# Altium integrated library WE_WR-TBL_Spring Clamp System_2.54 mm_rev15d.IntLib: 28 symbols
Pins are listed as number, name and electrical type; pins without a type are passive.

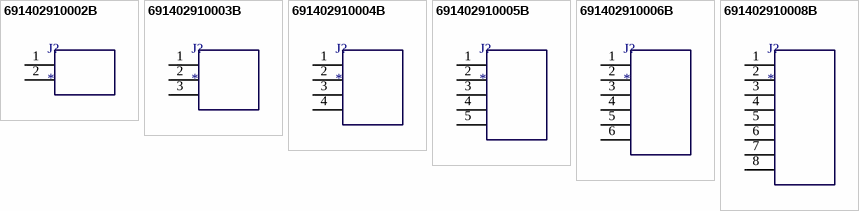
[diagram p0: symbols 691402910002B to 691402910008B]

## 691402910002B
designator J?
WR-TBL Screwless Entry Horizontal,Serie 4029 B - 2.54 mm; Manufacturer: Würth Elektronik eiSos GmbH; partNo: 691402910002B; ComponentLink1 Description: Manufacturer; ComponentLink2 Description: Datasheet; NoPins: 4
footprint 691402910002B
pins: 1  , 2  

## 691402910003B
designator J?
WR-TBL Screwless Entry Horizontal,Serie 4029 B - 2.54 mm; Manufacturer: Würth Elektronik eiSos GmbH; partNo: 691402910003B; ComponentLink1 Description: Manufacturer; ComponentLink2 Description: Datasheet; NoPins: 6
footprint 691402910003B
pins: 1  , 2  , 3  

## 691402910004B
designator J?
WR-TBL Screwless Entry Horizontal,Serie 4029 B - 2.54 mm; Manufacturer: Würth Elektronik eiSos GmbH; partNo: 691402910004B; ComponentLink1 Description: Manufacturer; ComponentLink2 Description: Datasheet; NoPins: 8
footprint 691402910004B
pins: 1  , 2  , 3  , 4  

## 691402910005B
designator J?
WR-TBL Screwless Entry Horizontal,Serie 4029 B - 2.54 mm; Manufacturer: Würth Elektronik eiSos GmbH; partNo: 691402910005B; ComponentLink1 Description: Manufacturer; ComponentLink2 Description: Datasheet; NoPins: 10
footprint 691402910005B
pins: 1  , 2  , 3  , 4  , 5  

## 691402910006B
designator J?
WR-TBL Screwless Entry Horizontal,Serie 4029 B - 2.54 mm; Manufacturer: Würth Elektronik eiSos GmbH; partNo: 691402910006B; ComponentLink1 Description: Manufacturer; ComponentLink2 Description: Datasheet; NoPins: 12
footprint 691402910006B
pins: 1  , 2  , 3  , 4  , 5  , 6  

## 691402910008B
designator J?
WR-TBL Screwless Entry Horizontal,Serie 4029 B - 2.54 mm; Manufacturer: Würth Elektronik eiSos GmbH; partNo: 691402910008B; ComponentLink1 Description: Manufacturer; ComponentLink2 Description: Datasheet; NoPins: 16
footprint 691402910008B
pins: 1  , 2  , 3  , 4  , 5  , 6  , 7  , 8  


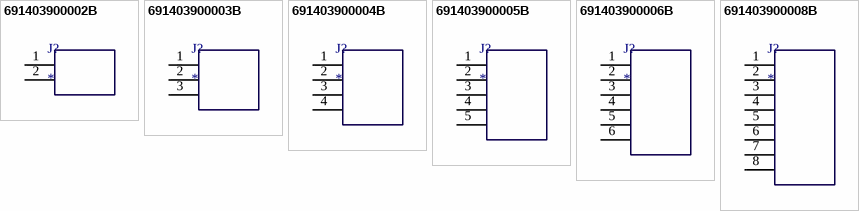
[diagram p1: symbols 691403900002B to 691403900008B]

## 691403900002B
designator J?
WR-TBL Screwless Entry Vertical,Serie 4039 B - 2.54 mm; Manufacturer: Würth Elektronik eiSos GmbH; partNo: 691403900002B; ComponentLink1 Description: Manufacturer; ComponentLink2 Description: Datasheet; NoPins: 4
footprint 691403900002B
pins: 1  , 2  

## 691403900003B
designator J?
WR-TBL Screwless Entry Vertical,Serie 4039 B - 2.54 mm; Manufacturer: Würth Elektronik eiSos GmbH; partNo: 691403900003B; ComponentLink1 Description: Manufacturer; ComponentLink2 Description: Datasheet; NoPins: 6
footprint 691403900003B
pins: 1  , 2  , 3  

## 691403900004B
designator J?
WR-TBL Screwless Entry Vertical,Serie 4039 B - 2.54 mm; Manufacturer: Würth Elektronik eiSos GmbH; partNo: 691403900004B; ComponentLink1 Description: Manufacturer; ComponentLink2 Description: Datasheet; NoPins: 8
footprint 691403900004B
pins: 1  , 2  , 3  , 4  

## 691403900005B
designator J?
WR-TBL Screwless Entry Vertical,Serie 4039 B - 2.54 mm; Manufacturer: Würth Elektronik eiSos GmbH; partNo: 691403900005B; ComponentLink1 Description: Manufacturer; ComponentLink2 Description: Datasheet; NoPins: 10
footprint 691403900005B
pins: 1  , 2  , 3  , 4  , 5  

## 691403900006B
designator J?
WR-TBL Screwless Entry Vertical,Serie 4039 B - 2.54 mm; Manufacturer: Würth Elektronik eiSos GmbH; partNo: 691403900006B; ComponentLink1 Description: Manufacturer; ComponentLink2 Description: Datasheet; NoPins: 12
footprint 691403900006B
pins: 1  , 2  , 3  , 4  , 5  , 6  

## 691403900008B
designator J?
WR-TBL Screwless Entry Vertical,Serie 4039 B - 2.54 mm; Manufacturer: Würth Elektronik eiSos GmbH; partNo: 691403900008B; ComponentLink1 Description: Manufacturer; ComponentLink2 Description: Datasheet; NoPins: 16
footprint 691403900008B
pins: 1  , 2  , 3  , 4  , 5  , 6  , 7  , 8  


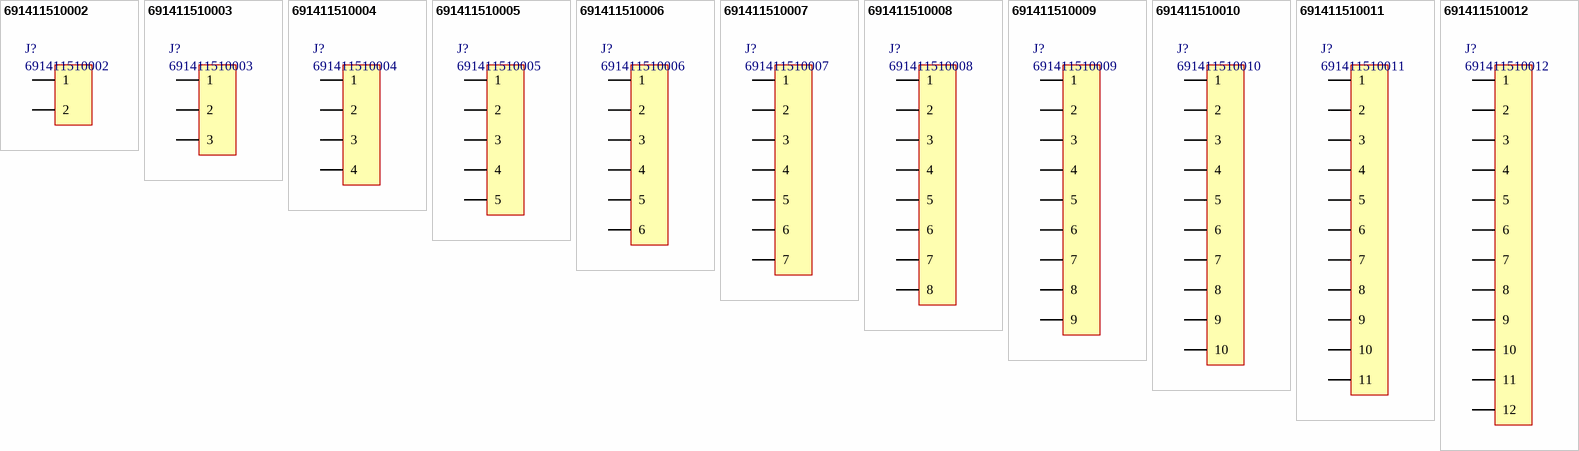
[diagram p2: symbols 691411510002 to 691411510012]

## 691411510002
designator J?
Horizontal Cable Entry Screwless, Serie 4115 - 5.08 mm; Manufacturer: Wurth Elektronik; ComponentLink1 Description: Manufacturer; ComponentLink2 Description: Datasheet; NoPins: 2
footprint 691411510002 (Serie 4115 - 5.08 mm _ 2 pins)
pins: 1, 2

## 691411510003
designator J?
Horizontal Cable Entry Screwless, Serie 4115 - 5.08 mm; Manufacturer: Wurth Elektronik; ComponentLink1 Description: Manufacturer; ComponentLink2 Description: Datasheet; NoPins: 3
footprint 691411510003 (Serie 4115 - 5.08 mm _ 3 pins)
pins: 1, 2, 3

## 691411510004
designator J?
Horizontal Cable Entry Screwless, Serie 4115 - 5.08 mm; Manufacturer: Wurth Elektronik; ComponentLink1 Description: Manufacturer; ComponentLink2 Description: Datasheet; NoPins: 4
footprint 691411510004 (Serie 4115 - 5.08 mm _ 4 pins)
pins: 1, 2, 3, 4

## 691411510005
designator J?
Horizontal Cable Entry Screwless, Serie 4115 - 5.08 mm; Manufacturer: Wurth Elektronik; ComponentLink1 Description: Manufacturer; ComponentLink2 Description: Datasheet; NoPins: 5
footprint 691411510005 (Serie 4115 - 5.08 mm _ 5 pins)
pins: 1, 2, 3, 4, 5

## 691411510006
designator J?
Horizontal Cable Entry Screwless, Serie 4115 - 5.08 mm; Manufacturer: Wurth Elektronik; ComponentLink1 Description: Manufacturer; ComponentLink2 Description: Datasheet; NoPins: 6
footprint 691411510006 (Serie 4115 - 5.08 mm _ 6 pins)
pins: 1, 2, 3, 4, 5, 6

## 691411510007
designator J?
Horizontal Cable Entry Screwless, Serie 4115 - 5.08 mm; Manufacturer: Wurth Elektronik; ComponentLink1 Description: Manufacturer; ComponentLink2 Description: Datasheet; NoPins: 7
footprint 691411510007 (Serie 4115 - 5.08 mm _ 7 pins)
pins: 1, 2, 3, 4, 5, 6, 7

## 691411510008
designator J?
Horizontal Cable Entry Screwless, Serie 4115 - 5.08 mm; Manufacturer: Wurth Elektronik; ComponentLink1 Description: Manufacturer; ComponentLink2 Description: Datasheet; NoPins: 8
footprint 691411510008 (Serie 4115 - 5.08 mm _ 8 pins)
pins: 1, 2, 3, 4, 5, 6, 7, 8

## 691411510009
designator J?
Horizontal Cable Entry Screwless, Serie 4115 - 5.08 mm; Manufacturer: Wurth Elektronik; ComponentLink1 Description: Manufacturer; ComponentLink2 Description: Datasheet; NoPins: 9
footprint 691411510009 (Serie 4115 - 5.08 mm _ 9 pins)
pins: 1, 2, 3, 4, 5, 6, 7, 8, 9

## 691411510010
designator J?
Horizontal Cable Entry Screwless, Serie 4115 - 5.08 mm; Manufacturer: Wurth Elektronik; ComponentLink1 Description: Manufacturer; ComponentLink2 Description: Datasheet; NoPins: 10
footprint 691411510010 (Serie 4115 - 5.08 mm _ 10 pins)
pins: 1, 2, 3, 4, 5, 6, 7, 8, 9, 10

## 691411510011
designator J?
Horizontal Cable Entry Screwless, Serie 4115 - 5.08 mm; Manufacturer: Wurth Elektronik; ComponentLink1 Description: Manufacturer; ComponentLink2 Description: Datasheet; NoPins: 11
footprint 691411510011 (Serie 4115 - 5.08 mm _ 11 pins)
pins: 1, 2, 3, 4, 5, 6, 7, 8, 9, 10, 11

## 691411510012
designator J?
Horizontal Cable Entry Screwless, Serie 4115 - 5.08 mm; Manufacturer: Wurth Elektronik; ComponentLink1 Description: Manufacturer; ComponentLink2 Description: Datasheet; NoPins: 12
footprint 691411510012 (Serie 4115 - 5.08 mm _ 12 pins)
pins: 1, 2, 3, 4, 5, 6, 7, 8, 9, 10, 11, 12


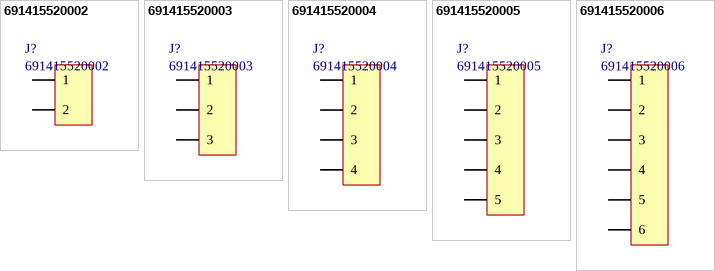
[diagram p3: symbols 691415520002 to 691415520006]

## 691415520002
designator J?
45° Cable Entry Screwless, Serie 4155 - 5.08 mm; Manufacturer: Wurth Elektronik; ComponentLink1 Description: Manufacturer; ComponentLink2 Description: Datasheet; NoPins: 2
footprint 691415520002 (Serie 4155 - 5.08 mm _ 2 pins)
pins: 1, 2

## 691415520003
designator J?
45° Cable Entry Screwless, Serie 4155 - 5.08 mm; Manufacturer: Wurth Elektronik; ComponentLink1 Description: Manufacturer; ComponentLink2 Description: Datasheet; NoPins: 3
footprint 691415520003 (Serie 4155 - 5.08 mm _ 3 pins)
pins: 1, 2, 3

## 691415520004
designator J?
45° Cable Entry Screwless, Serie 4155 - 5.08 mm; Manufacturer: Wurth Elektronik; ComponentLink1 Description: Manufacturer; ComponentLink2 Description: Datasheet; NoPins: 4
footprint 691415520004 (Serie 4155 - 5.08 mm _ 4 pins)
pins: 1, 2, 3, 4

## 691415520005
designator J?
45° Cable Entry Screwless, Serie 4155 - 5.08 mm; Manufacturer: Wurth Elektronik; ComponentLink1 Description: Manufacturer; ComponentLink2 Description: Datasheet; NoPins: 5
footprint 691415520005 (Serie 4155 - 5.08 mm _ 5 pins)
pins: 1, 2, 3, 4, 5

## 691415520006
designator J?
45° Cable Entry Screwless, Serie 4155 - 5.08 mm; Manufacturer: Wurth Elektronik; ComponentLink1 Description: Manufacturer; ComponentLink2 Description: Datasheet; NoPins: 6
footprint 691415520006 (Serie 4155 - 5.08 mm _ 6 pins)
pins: 1, 2, 3, 4, 5, 6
